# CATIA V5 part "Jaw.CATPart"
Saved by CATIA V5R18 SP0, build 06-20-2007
Part number: Part 2
Bounding box of the stored display mesh (mm): x 0 to 20, y -45 to 45, z -25 to 40
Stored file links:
  D:\Shriniwas\v5_r19\c16_CAT_v5r19\c16_Part\Presmatic Joint\Jaw.CATPart
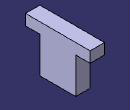
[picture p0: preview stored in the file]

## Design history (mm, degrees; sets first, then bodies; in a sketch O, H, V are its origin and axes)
Body1 (main body)
  Sketch1 on yz-plane, origin (0, 0, 0), H (0, 1, 0), V (0, 0, 1)
    line L1 (25, 25) -> (25, -25)
    line L2 (25, -25) -> (-25, -25)
    line L3 (-25, -25) -> (-25, 25)
    point P1 (25, 25)
    point P4 (-25, 25)
    line L4 (-25, 25) -> (-45, 25)
    point P5 (-45, 25)
    line L5 (-45, 25) -> (-45, 40)
    line L6 (-45, 40) -> (45, 40)
    line L7 (25, 25) -> (45, 25)
    point P8 (45, 25)
    line L8 (45, 25) -> (45, 40)
    reference intersected line E1 through (0, 0) direction (-1, 0) from xy-plane
    reference intersected line E3 through (0, 0) direction (0, 1) from zx-plane
    length L1 = 50
    distance V L1 = 25
    distance H L2 = 25
    distance E1 L6 = 40
    distance P1 P8 = 20
    distance P4 P5 = 20
    vertical: L1 V, L3 V, L5 V, L8 V, E3 V
    horizontal: L2 H, L4 H, L6 H, L7 H, E1 H
    equidistance: L1 L3 O
    perpendicularity: E1 L1
    coincidence: P1 L4, P4 L7, P5 L7, P8 L4, L4 L7
  Pad1: profile Sketch1, direction (1, 0, 0), length 20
